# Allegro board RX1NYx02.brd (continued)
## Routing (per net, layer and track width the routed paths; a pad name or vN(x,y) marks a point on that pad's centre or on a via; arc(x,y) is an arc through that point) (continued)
GND_SIGNAL: length 26.8
  GND w0.254: 122.16,-86.62 J_S2D_TOP.1 ; J_S2D_TOP.1 123.08,-86.62 ; J_S2D_TOP.1 122.62,-87.84 ; J_S2D_TOP.1 122.62,-85.4 ; J_S2D_BOT.1 122.62,-94.29 ; J_S2D_BOT.1 123.08,-95.51 ; J_S2D_BOT.1 122.62,-96.73 ; J_S2D_BOT.1 122.16,-95.51
  VCC w0.254: 122.62,-96.73 J_S2D_BOT.1 ; J_S2D_BOT.1 123.08,-95.51 ; J_S2D_BOT.1 122.62,-94.29 ; J_S2D_BOT.1 122.16,-95.51 ; 122.16,-86.62 J_S2D_TOP.1 ; J_S2D_TOP.1 122.62,-85.4 ; J_S2D_TOP.1 122.62,-87.84 ; J_S2D_TOP.1 123.08,-86.62
  GD2 w0.254: 122.62,-96.73 J_S2D_BOT.1 ; J_S2D_BOT.1 123.08,-95.51 ; J_S2D_BOT.1 122.16,-95.51 ; J_S2D_BOT.1 122.62,-94.29 ; 122.62,-87.84 J_S2D_TOP.1 ; J_S2D_TOP.1 122.16,-86.62 ; J_S2D_TOP.1 123.08,-86.62 ; J_S2D_TOP.1 122.62,-85.4
  GD3 w0.254: J_S2D_TOP.1 123.08,-86.62 ; J_S2D_TOP.1 122.62,-85.4 ; J_S2D_TOP.1 122.62,-87.84 ; J_S2D_TOP.1 122.16,-86.62 ; 122.16,-95.51 J_S2D_BOT.1 ; J_S2D_BOT.1 123.08,-95.51 ; J_S2D_BOT.1 122.62,-94.29 ; J_S2D_BOT.1 122.62,-96.73
BD1_555_DISCHARGE: length 2.3
  TOP w0.254: R13.1 107.94,-33.08 ; R13.1 107.61,-33.4 ; R13.1 107.94,-33.73 ; R11.1 107.76,-33.86 ; R11.1 107.33,-34.29 ; R11.1 107.76,-34.73
BD1_555_OUT: length 2.4
  TOP w0.102: U4.3 R16.2 R18.2
BD1_555_OUT_JP: length 6
  TOP w0.102: P3.1 95.11,-33.53 96.38,-34.8 R16.1
BD1_555_RST_N: length 3.5
  TOP w0.102: C7.1 99.63,-36.91 99.43,-36.71 99.3,-36.71 99.17,-36.58 R15.1 99.43,-36.33 99.68,-36.07 U4.4
BD1_555_TRI: length 27.8
  TOP w0.102: R14.2 U4.2 102.22,-33.53 102.73,-34.04 102.73,-38.1 101.46,-39.37 97.14,-39.37 96.38,-40.14 96.38,-50.04 95.62,-50.8 R8.2
BD1_AUX_PWR_EN: length 7.1
  TOP w0.102: TP26.TEST 6.15,-29.47 5.18,-28.5 P_OCP1.B12
BD1_BIF0_N: length 7.4
  TOP w0.102: P_OCP1.B7 6.52,-25.5 7.63,-24.39 TP18.TEST
BD1_BIF1_N: length 10.5
  TOP w0.102: TP20.TEST 10.72,-24.59 9.65,-25.66 7.18,-25.66 6.74,-26.1 P_OCP1.B8
BD1_BIF2_N: length 6.8
  TOP w0.102: TP22.TEST 8.85,-26.9 7.51,-26.9 7.3,-26.7 P_OCP1.B9
BD1_BTN_NC: length 16.6
  TOP w0.102: U1.1 91.61,-48.28 91.81,-48.48 v1(91.81,-48.9) ; SW1.1 92.19,-40.77 91.42,-40.01 v1(91.42,-39.5) 91.17,-39.25 R7.1 R9.1
  BOTTOM w0.102: v1(91.81,-48.9) 92.44,-48.26 92.44,-40.52 v1(91.42,-39.5)
BD1_BTN_NO: length 14.3
  TOP w0.102: R17.1 94.02,-51.39 93.94,-51.31 93.46,-51.31 93.33,-51.19 R8.1 93.33,-50.8 93.33,-50.42 93.5,-50.26 SW1.3 93.5,-46.02 93.08,-45.6 91.81,-45.6 91.04,-44.83 91.04,-44.07 91.93,-43.18 91.93,-41.79 91.42,-41.28 U6.2
BD1_BUS_SEL: length 53.9
  TOP w0.102: R7.2 91.67,-38.36 92.06,-37.98 95.49,-37.98 v1(98.03,-35.44) R18.1 ; P13.1 96.07,-26.42 R158.1 96.58,-27.51 96.89,-27.82 97.39,-27.82 97.6,-28.02 C163.2 98.41,-28.96 98.57,-29.12 Q1.1 102.54,-30.42 v1(102.47,-30.48) ; U26.2 92.04,-57.52 v1(92.33,-57.23)
  BOTTOM w0.102: v1(102.47,-30.48) 100.31,-32.64 100.31,-33.15 v1(98.03,-35.44) 94.47,-38.99 94.47,-56.21 93.58,-57.1 92.46,-57.1 v1(92.33,-57.23)
BD1_CLK_NCSI: length 7.2
  BOTTOM w0.102: TP17.TEST 7.73,-18.67 6.56,-17.5 P_OCP1.OCP_A14
BD1_MAIN_PWR_EN: length 11.8
  TOP w0.102: TP27.TEST 8.32,-7.24 7.56,-8 7.56,-9.02 6.28,-10.3 P_OCP1.OCP_B2
BD1_NCSI_ARBIN: length 10.4
  BOTTOM w0.102: TP8.TEST 7.99,-12.32 7.17,-11.5 P_OCP1.OCP_A4
BD1_NCSI_ARBOUT: length 7.4
  BOTTOM w0.102: TP9.TEST 7.93,-13.59 6.44,-12.1 P_OCP1.OCP_A5
BD1_NCSI_CRS_DV: length 10.6
  TOP w0.102: P_OCP1.OCP_B14 6.64,-17.5 7.43,-18.29 10.22,-18.29 11.11,-17.4 TP16.TEST
BD1_NCSI_RXD0: length 7.4
  TOP w0.102: P_OCP1.OCP_B9 6.3,-14.5 7.93,-16.13 TP14.TEST
BD1_NCSI_RXD1: length 10.3
  TOP w0.102: TP12.TEST 7.68,-14.86 6.72,-13.9 P_OCP1.OCP_B8
BD1_NCSI_TXD0: length 11.6
  BOTTOM w0.102: P_OCP1.OCP_A9 6.36,-14.5 6.97,-15.12 6.97,-16.01 7.86,-16.89 10.72,-16.89 11.22,-17.4 TP15.TEST
BD1_NCSI_TXD1: length 8.1
  BOTTOM w0.102: P_OCP1.OCP_A8 6.52,-13.9 7.45,-14.84 7.45,-15.65 7.93,-16.13 TP13.TEST
BD1_NCSI_TXEN: length 10.8
  BOTTOM w0.102: TP11.TEST 8.24,-14.86 6.68,-13.3 P_OCP1.OCP_A7
BD1_NIC_PWR_GOOD: length 8.6
  TOP w0.102: P_OCP1.OCP_B1 6.11,-9.7 7.18,-8.64 7.18,-8 8.75,-6.43 R5.1
BD1_PERST0_N: length 10.7
  TOP w0.102: TP24.TEST 10.79,-27.13 10.03,-27.9 7.38,-27.9 6.78,-27.3 P_OCP1.B10
BD1_PERST1_N: length 10.8
  BOTTOM w0.102: TP25.TEST 11.18,-27.13 10.16,-28.15 7.5,-28.15 6.81,-27.46 3.61,-27.46 3.17,-27.9 P_OCP1.A11
BD1_PERST2_N: length 7.4
  BOTTOM w0.102: TP3.TEST 6.97,-8.51 5.78,-9.7 P_OCP1.OCP_A1
BD1_PERST3_N: length 10.1
  BOTTOM w0.102: TP4.TEST 6.33,-9.78 5.82,-10.3 P_OCP1.OCP_A2
BD1_PRSNTA_N: length 61.8
  TOP w0.102: v1(8.25,-54.44) 8.5,-54.69 R1.2 R2.2 8.5,-56.53 7.49,-57.55 7.49,-69.42 8.25,-70.19 9.91,-70.19 10.14,-70.42 R6.2 ; R3.2 v1(12.95,-28.4)
  VCC w0.102: v1(8.25,-54.44) 9.89,-52.8 9.89,-47.63 12.94,-44.58 12.94,-28.42 v1(12.95,-28.4)
  BOTTOM w0.102: v1(12.95,-28.4) 13.21,-28.15 13.21,-26.75 12.83,-26.37 11.05,-26.37 9.73,-27.69 7.8,-27.69 7.11,-27 3.43,-27 3.14,-27.3 P_OCP1.A10
BD1_PRSNTB0_N: length 10
  TOP w0.102: P_OCP1.B42 6.19,-49.91 7.75,-51.46 7.75,-54.82 8.01,-55.07
BD1_PRSNTB1_N: length 11.9
  TOP w0.102: 8.01,-55.71 v1(6.99,-55.71)
  BOTTOM w0.102: P_OCP1.A42 6.26,-49.91 7.81,-51.45 7.81,-54.25 6.99,-55.07 v1(6.99,-55.71)
BD1_PRSNTB2_N: length 9.8
  TOP w0.102: R3.1 v1(11.18,-28.4)
  BOTTOM w0.102: v1(11.18,-28.4) 10.92,-28.66 7.37,-28.66 7.21,-28.5 P_OCP1.A12
BD1_PRSNTB3_N: length 7.8
  TOP w0.102: P_OCP1.B70 6.95,-71.02 7.1,-70.87 R6.1
BD1_PWRBRK_N: length 8.1
  TOP w0.102: R164.1 v1(8.32,-69.47)
  BOTTOM w0.102: v1(8.32,-69.47) 6.78,-71.02 P_OCP1.A70
BD1_REFCLK0_DN: length 104.7
  TOP w0.099: 18.48,-21.58 18.59,-21.72 18.7,-21.74 21.2,-21.3 24.35,-21.86 26.85,-21.42 28.55,-21.72 31.05,-21.28 34.94,-21.96 38.58,-21.32 40.5,-21.66 42.98,-21.22 45.48,-21.66 48.38,-21.15 50.88,-21.59 53.72,-21.09 55.99,-21.49 61.36,-20.54 61.53,-20.31 ; 47.59,-13.36 47.59,-13.07 46.55,-12.03 46.16,-9.81 46.16,-9.25 46.06,-9.15 ; 18.25,-21.54 18.11,-21.64 16.07,-21.28 14.15,-21.62 13.7,-22.07 13.32,-24.3 13.58,-25.82 13.58,-27.4 13.26,-29.24 12.49,-30 8.66,-30.67 3.77,-29.82 3.27,-29.82 3.15,-29.7 P_OCP1.B14 ; 47.73,-13.5 48.02,-13.5 48.57,-14.05 49.48,-14.21 51.49,-13.85 53.99,-14.3 56.19,-13.91 59.01,-14.41 59.18,-14.64 ; 61.73,-20.27 61.96,-20.44 64.27,-20.03 66.21,-18.1 66.21,-16.98 64.62,-15.4 59.61,-14.51 59.38,-14.68
  TOP w0.152: 47.73,-13.5 47.59,-13.36 ; 61.53,-20.31 61.73,-20.27 ; 18.25,-21.54 18.48,-21.58 ; 46.06,-9.15 P_BD1_CLK0_N.1 ; 59.38,-14.68 59.18,-14.64
BD1_REFCLK0_DP: length 104.6
  TOP w0.099: 46.62,-9.15 46.52,-9.25 46.52,-9.78 46.88,-11.86 48,-12.98 ; 48.15,-13.12 48.74,-13.72 49.48,-13.85 51.49,-13.49 53.99,-13.93 56.19,-13.55 59.26,-14.09 ; P_OCP1.B15 3.15,-30.3 3.27,-30.17 3.74,-30.17 8.66,-31.03 12.66,-30.34 13.59,-29.41 13.94,-27.43 13.94,-25.79 13.68,-24.29 14.03,-22.24 14.33,-21.95 16.07,-21.64 18.18,-22.01 ; 59.5,-14.13 64.8,-15.06 66.56,-16.83 66.56,-18.24 64.44,-20.36 61.84,-20.82 ; 61.57,-20.87 55.99,-21.85 53.72,-21.45 50.88,-21.95 48.38,-21.51 45.48,-22.02 42.98,-21.58 40.5,-22.02 38.58,-21.68 34.94,-22.32 31.05,-21.64 28.55,-22.08 26.85,-21.78 24.35,-22.22 21.2,-21.66 18.7,-22.11 18.38,-22.05
  TOP w0.152: 59.26,-14.09 59.5,-14.13 ; 18.38,-22.05 18.18,-22.01 ; 61.84,-20.82 61.57,-20.87 ; 48,-12.98 48.15,-13.12 ; P_BD1_CLK0_P.1 46.62,-9.15
BD1_REFCLK1_DN: length 104.6
  BOTTOM w0.099: P_OCP1.A14 3.15,-29.7 3.25,-29.8 3.68,-29.8 4.74,-29.98 7.68,-29.46 10.24,-29.92 12.75,-29.48 15.25,-29.92 17.75,-29.48 20.25,-29.92 22.75,-29.48 25.25,-29.92 27.75,-29.48 30.56,-29.97 33.34,-29.48 34.72,-28.09 35.66,-22.72 36.25,-22.13 68.81,-16.39 69,-16.12 ; 91.03,-10.83 91.03,-11.15 89.44,-12.75 83.89,-13.73 83.63,-13.55 ; 69.14,-16.09 69.41,-16.28 83.29,-13.83 83.47,-13.58 ; 91.14,-10.72 91.47,-10.72 91.77,-10.42 91.88,-9.75 91.88,-9.25 91.79,-9.15
  BOTTOM w0.152: 83.63,-13.55 83.47,-13.58 ; 69.14,-16.09 69,-16.12 ; P_BD1_CLK1_N.1 91.79,-9.15 ; 91.14,-10.72 91.03,-10.83
BD1_REFCLK1_DP: length 104.6
  BOTTOM w0.099: 69.26,-16.67 83.52,-14.15 ; 91.55,-11.14 92.1,-10.59 92.24,-9.78 92.24,-9.25 92.34,-9.15 ; P_OCP1.A15 3.15,-30.3 3.29,-30.15 3.65,-30.15 4.74,-30.34 7.68,-29.83 10.24,-30.28 12.75,-29.84 15.25,-30.28 17.75,-29.84 20.25,-30.28 22.75,-29.84 25.25,-30.28 27.75,-29.84 30.56,-30.33 33.51,-29.81 35.05,-28.27 35.99,-22.89 36.42,-22.46 69.06,-16.7 ; 83.79,-14.11 89.61,-13.08 91.4,-11.29
  BOTTOM w0.152: 92.34,-9.15 P_BD1_CLK1_P.1 ; 91.4,-11.29 91.55,-11.14 ; 69.06,-16.7 69.26,-16.67 ; 83.52,-14.15 83.79,-14.11
BD1_REFCLK2_DN: length 104.7
  TOP w0.099: 56.1,-16.78 56.24,-16.68 57.24,-16.86 57.84,-17.45 57.84,-18.09 57.1,-18.83 52.3,-19.67 49.15,-19.11 47.79,-19.35 44.31,-18.74 41.74,-19.19 39.29,-18.76 36.67,-19.22 35.06,-18.94 30.2,-19.8 29.87,-19.74 27.59,-17.46 17.86,-15.77 15.28,-16.22 12.89,-15.8 11.06,-16.12 10.13,-17.05 9.44,-17.17 7.72,-17.17 6.85,-16.3 4.09,-15.82 3.27,-15.82 3.15,-15.7 P_OCP1.OCP_B11 ; 45.98,-16.67 45.82,-16.44 45.29,-16.34 42.79,-16.78 40.29,-16.34 37.79,-16.78 35.28,-16.34 32.78,-16.78 31.82,-16.62 31.58,-16.78 ; 46.18,-16.71 46.42,-16.54 47.79,-16.78 50.29,-16.34 52.79,-16.78 54.8,-16.43 55.86,-16.62 55.96,-16.76 ; 23.2,-9.15 23.3,-9.25 23.3,-9.67 23.78,-12.43 24.23,-12.88 24.23,-13.17 ; 31.38,-16.75 31.22,-16.51 27.16,-15.8 24.67,-13.31 24.38,-13.31
  TOP w0.152: P_BD1_CLK2_N.1 23.2,-9.15 ; 24.23,-13.17 24.38,-13.31 ; 55.96,-16.76 56.1,-16.78 ; 31.38,-16.75 31.58,-16.78 ; 45.98,-16.67 46.18,-16.71
BD1_REFCLK2_DP: length 104.7
  TOP w0.099: 24.83,-12.97 27.33,-15.47 31.45,-16.19 ; 46.05,-16.12 45.29,-15.98 42.79,-16.42 40.29,-15.98 37.79,-16.42 35.28,-15.98 32.78,-16.42 31.73,-16.24 ; 24.62,-12.76 24.11,-12.25 23.66,-9.64 23.66,-9.25 23.76,-9.15 ; P_OCP1.OCP_B12 3.15,-16.3 3.27,-16.18 4.05,-16.18 6.68,-16.64 7.57,-17.53 9.47,-17.53 10.31,-17.38 11.24,-16.45 12.89,-16.16 15.28,-16.58 17.86,-16.13 27.42,-17.79 29.7,-20.07 30.2,-20.16 35.06,-19.3 36.67,-19.58 39.29,-19.12 41.74,-19.55 44.31,-19.1 47.79,-19.71 49.15,-19.47 52.3,-20.03 57.27,-19.16 58.19,-18.24 58.19,-17.31 57.42,-16.53 56.22,-16.32 ; 46.32,-16.16 47.79,-16.42 50.29,-15.98 52.79,-16.42 54.8,-16.07 56.02,-16.28
  TOP w0.152: P_BD1_CLK2_P.1 23.76,-9.15 ; 46.05,-16.12 46.32,-16.16 ; 56.02,-16.28 56.22,-16.32 ; 31.45,-16.19 31.73,-16.24 ; 24.62,-12.76 24.83,-12.97
BD1_REFCLK3_DN: length 104.6
  BOTTOM w0.099: 52.66,-14.71 52.41,-14.89 52.1,-14.84 49.6,-15.28 47.99,-15 47.1,-14.84 44.6,-15.28 42.1,-14.84 39.59,-15.28 37.09,-14.84 34.59,-15.28 32.41,-14.9 30.82,-15.18 28.31,-14.74 25.23,-15.28 22.73,-14.84 20.96,-15.15 20.5,-15.62 20.5,-16.62 21.32,-17.44 23.37,-17.81 29.32,-16.76 31.31,-17.11 31.93,-17.73 31.93,-17.99 30.96,-18.96 27.91,-19.49 23.84,-18.78 21.34,-19.22 18.83,-18.78 16.33,-19.22 12.96,-18.62 12.18,-18.76 11.32,-18.76 9.91,-17.35 9.63,-17.35 8.63,-17.53 7.62,-17.35 6.56,-16.29 3.87,-15.82 3.27,-15.82 3.15,-15.7 P_OCP1.OCP_A11 ; 68.56,-11.01 68.74,-11.26 68.47,-12.87 66.26,-15.07 64.84,-15.32 63.38,-15.06 63.2,-14.81 ; 52.83,-14.74 53.01,-15 54.6,-15.28 57.1,-14.84 59.61,-15.28 62.11,-14.84 62.78,-14.96 63.03,-14.78 ; 68.93,-9.15 69.02,-9.25 69.02,-9.65 68.85,-10.66 68.59,-10.84
  BOTTOM w0.152: 68.59,-10.84 68.56,-11.01 ; 52.83,-14.74 52.66,-14.71 ; 63.2,-14.81 63.03,-14.78 ; P_BD1_CLK3_N.1 68.93,-9.15
BD1_REFCLK3_DP: length 104.7
  BOTTOM w0.099: P_OCP1.OCP_A12 3.15,-16.3 3.27,-16.18 3.83,-16.18 6.39,-16.62 7.45,-17.68 8.63,-17.89 9.66,-17.71 9.76,-17.71 11.17,-19.12 12.21,-19.12 12.96,-18.98 16.33,-19.58 18.83,-19.14 21.34,-19.58 23.84,-19.14 27.91,-19.85 31.13,-19.29 32.28,-18.14 32.28,-17.58 31.48,-16.78 29.32,-16.4 23.37,-17.44 21.49,-17.11 20.85,-16.48 20.85,-15.76 21.14,-15.48 22.73,-15.2 25.23,-15.64 28.31,-15.1 30.82,-15.54 32.41,-15.26 34.59,-15.64 37.09,-15.2 39.59,-15.64 42.1,-15.2 44.6,-15.64 47.1,-15.2 49.6,-15.64 52.1,-15.2 52.54,-15.28 ; 69.17,-10.91 69.38,-9.68 69.38,-9.25 69.48,-9.15 ; 62.91,-15.34 62.11,-15.2 59.61,-15.64 57.1,-15.2 54.6,-15.64 52.76,-15.32 ; 63.13,-15.38 64.84,-15.68 66.44,-15.4 68.8,-13.04 69.13,-11.13
  BOTTOM w0.152: 69.13,-11.13 69.17,-10.91 ; 62.91,-15.34 63.13,-15.38 ; 52.54,-15.28 52.76,-15.32 ; 69.48,-9.15 P_BD1_CLK3_P.1
BD1_SCAN_CLK: length 10.2
  TOP w0.102: P_OCP1.OCP_B6 3.13,-12.7 3.63,-12.2 11,-12.2 11.12,-12.32 TP1.TEST
BD1_SCAN_DATA_IN: length 10.8
  TOP w0.102: P_OCP1.OCP_B4 3.18,-11.5 3.51,-11.18 6.54,-11.18 7.94,-9.78 TP7.TEST
BD1_SCAN_DATA_OUT: length 7.2
  TOP w0.102: P_OCP1.OCP_B5 3.09,-12.1 3.51,-11.69 6.67,-11.69 7.3,-11.05 TP10.TEST
BD1_SCAN_LD_N: length 8.1
  TOP w0.102: P_OCP1.OCP_B3 3.15,-10.9 3.38,-10.67 6.41,-10.67 7.81,-9.27 7.81,-8.64 7.94,-8.51 TP5.TEST
BD1_SLOT_ID: length 7.1
  TOP w0.102: TP2.TEST 7.6,-13.59 7.31,-13.3 P_OCP1.OCP_B7
BD1_SMB_CLK: length 7.5
  BOTTOM w0.102: TP19.TEST 7.95,-24.39 6.7,-25.63 5.02,-25.63 4.88,-25.5 P_OCP1.A7
BD1_SMB_RST_N: length 7
  BOTTOM w0.102: P_OCP1.A9 3.1,-26.7 3.25,-26.55 7.3,-26.55 7.68,-26.93 TP23.TEST
BD1_SMB_SDA: length 10.5
  BOTTOM w0.102: TP21.TEST 10.79,-24.59 9.73,-25.66 7.81,-25.66 7.37,-26.1 P_OCP1.A8
BD1_WAKE_N: length 6.8
  BOTTOM w0.102: TP6.TEST 7.43,-11.05 7.28,-10.9 P_OCP1.OCP_A3
BD2_555_OUT: length 2.4
  TOP w0.102: U20.3 R93.2 R95.2
BD2_555_OUT_JP: length 6
  TOP w0.102: P9.1 183.02,-47.19 181.75,-45.92 R93.1
BD2_555_RST_N: length 3.5
  TOP w0.102: C81.1 178.45,-43.81 178.66,-44.02 178.78,-44.02 178.91,-44.15 R92.1 178.66,-44.4 178.4,-44.65 U20.4
BD2_555_TRI: length 27.8
  TOP w0.102: R85.2 182.47,-29.92 181.7,-30.68 181.7,-40.59 180.94,-41.35 176.62,-41.35 175.35,-42.62 175.35,-46.69 175.86,-47.19 U20.2 R91.2
BD2_AUX_PWR_EN: length 7.1
  TOP w0.102: TP81.TEST 270.65,-51.26 271.62,-52.23 P_OCP2.B12
BD2_BIF0_N: length 7.4
  TOP w0.102: TP72.TEST 270.52,-56.34 271.63,-55.23 P_OCP2.B7
BD2_BIF1_N: length 10.1
  TOP w0.102: TP73.TEST 266.04,-55.06 271.03,-55.06 271.47,-54.63 P_OCP2.B8
BD2_BIF2_N: length 6.8
  TOP w0.102: TP77.TEST 270.42,-53.8 270.65,-54.03 P_OCP2.B9
BD2_BTN_NC: length 16.6
  TOP w0.102: R86.1 R84.1 186.91,-41.47 v1(186.69,-41.26) 186.69,-40.75 185.9,-39.95 SW3.1 ; v1(186.31,-31.96) 186.8,-32.45 U17.1
  BOTTOM w0.102: v1(186.31,-31.96) 185.17,-33.1 185.17,-38.56 186.69,-40.09 v1(186.69,-41.26)
BD2_BTN_NO: length 14.3
  TOP w0.102: U22.2 186.66,-39.45 186.15,-38.94 186.15,-37.54 187.04,-36.65 187.04,-35.89 186.28,-35.13 185.01,-35.13 184.59,-34.71 SW3.3 184.59,-30.47 184.75,-30.3 184.75,-29.93 R85.1 184.75,-29.54 184.63,-29.41 184.14,-29.41 184.07,-29.34 R94.1
BD2_BUS_SEL: length 34.8
  TOP w0.102: v1(173.36,-50.25) 173.38,-50.28 Q3.1 173.54,-51.77 C165.2 178.33,-52.42 179.34,-53.44 R160.1 180.21,-53.8 180.71,-54.31 P15.1 184.73,-54.32 U27.2 ; R84.2 185.77,-42.63 183.9,-42.63 181.66,-44.86 180.52,-44.86 v1(180.09,-45.29) 180.08,-45.29 R95.1
  BOTTOM w0.102: v1(180.09,-45.29) 178.31,-45.29 v1(173.36,-50.25)
BD2_CLK_NCSI: length 7.1
  BOTTOM w0.102: P_OCP2.OCP_A14 271.68,-63.22 270.64,-62.19 TP71.TEST
BD2_MAIN_PWR_EN: length 11.8
  TOP w0.102: P_OCP2.OCP_B2 272.82,-70.42 272.56,-70.69 271.54,-70.69 270.52,-71.7 270.52,-72.72 269.76,-73.48 TP56.TEST
BD2_NCSI_ARBIN: length 10.4
  BOTTOM w0.102: P_OCP2.OCP_A4 270.92,-69.22 270.1,-68.4 TP74.TEST
BD2_NCSI_ARBOUT: length 7.4
  BOTTOM w0.102: P_OCP2.OCP_A5 271.64,-68.62 270.15,-67.13 TP62.TEST
BD2_NCSI_CRS_DV: length 10.7
  TOP w0.102: TP70.TEST 266.97,-63.32 267.96,-62.34 270.56,-62.34 271.23,-63.02 274.59,-63.02 274.79,-63.22 P_OCP2.OCP_B14
BD2_NCSI_RXD0: length 7.4
  TOP w0.102: TP68.TEST 270.15,-64.59 271.78,-66.22 P_OCP2.OCP_B9
BD2_NCSI_RXD1: length 10.3
  TOP w0.102: P_OCP2.OCP_B8 273.27,-66.82 273.06,-66.62 270.6,-66.62 269.84,-65.86 TP66.TEST
BD2_NCSI_TXD0: length 11.6
  BOTTOM w0.102: TP69.TEST 266.97,-63.32 267.48,-63.83 270.22,-63.83 271.11,-64.72 271.11,-65.61 271.73,-66.22 P_OCP2.OCP_A9
BD2_NCSI_TXD1: length 8.3
  BOTTOM w0.102: TP67.TEST 270.27,-64.59 270.65,-64.97 270.65,-65.99 271.49,-66.82 P_OCP2.OCP_A8
BD2_NCSI_TXEN: length 10.8
  BOTTOM w0.102: P_OCP2.OCP_A7 271.4,-67.42 269.84,-65.86 TP65.TEST
BD2_NIC_PWR_GOOD: length 9
  TOP w0.102: R79.1 269.87,-74.37 270.93,-73.31 270.93,-71.86 271.64,-71.15 272.71,-71.15 272.84,-71.02 P_OCP2.OCP_B1
BD2_PE_OCP_CPU_0_DN: length 104.8
  BOTTOM w0.127: 203.17,-49.37 203.29,-49.24 203.5,-49.24 207.02,-48.63 207.79,-47.87 208.47,-43.96 209.05,-43.38 209.64,-43.38 209.99,-43.72 210.11,-44.44 209.77,-46.4 210.21,-48.9 209.77,-51.4 210.21,-53.9 209.78,-56.34 210.14,-58.38 211.1,-59.34 216.06,-60.2 218.29,-59.81 220.79,-60.25 223.29,-59.81 225.79,-60.25 228.29,-59.81 230.79,-60.25 233.3,-59.81 235.8,-60.25 238.3,-59.81 239.52,-60.03 241.48,-60.03 242.49,-59.02 243.56,-52.94 245.65,-50.85 248.58,-50.34 251.08,-50.78 253.58,-50.34 255.25,-50.63 266.17,-48.71 269.94,-49.37 272.93,-48.84 274.28,-49.08 274.78,-49.08 274.93,-49.23 P_OCP2.A17
  BOTTOM w0.152: BD2_P_OCP_CPU_0_N.1 203.17,-50.73 203.17,-49.37
BD2_PE_OCP_CPU_0_DP: length 104.8
  BOTTOM w0.127: 203.17,-48.81 203.29,-48.94 203.47,-48.94 206.88,-48.35 207.51,-47.72 208.18,-43.82 208.93,-43.07 209.77,-43.07 210.27,-43.58 210.42,-44.44 210.08,-46.4 210.52,-48.9 210.08,-51.4 210.52,-53.9 210.09,-56.34 210.42,-58.23 211.25,-59.06 216.06,-59.89 218.29,-59.5 220.79,-59.94 223.29,-59.5 225.79,-59.94 228.29,-59.5 230.79,-59.94 233.3,-59.5 235.8,-59.94 238.3,-59.5 239.55,-59.72 241.35,-59.72 242.2,-58.87 243.22,-53.12 243.27,-52.79 245.51,-50.56 247.06,-50.29 248.58,-50.03 251.08,-50.47 253.58,-50.03 255.25,-50.32 266.17,-48.4 269.94,-49.06 272.93,-48.53 274.31,-48.77 274.78,-48.77 274.93,-48.63 P_OCP2.A18
  BOTTOM w0.152: 203.17,-48.81 203.17,-47.45 BD2_P_OCP_CPU_0_P.1
BD2_PERST0_N: length 10.5
  TOP w0.102: P_OCP2.B10 270.77,-53.43 269.87,-52.53 TP79.TEST
BD2_PERST1_N: length 10.4
  BOTTOM w0.102: TP80.TEST 266.11,-52.61 271.27,-52.61 271.93,-53.26 274.48,-53.26 274.91,-52.83 P_OCP2.A11
BD2_PERST2_N: length 7.4
  BOTTOM w0.102: P_OCP2.OCP_A1 271.46,-71.02 270.27,-72.21 TP55.TEST
BD2_PERST3_N: length 10.1
  BOTTOM w0.102: TP57.TEST 270.52,-70.94 271.04,-70.42 P_OCP2.OCP_A2
BD2_PRSNTA_N: length 67.2
  TOP w0.102: R82.2 v1(267.97,-5.54) ; v1(270.73,-33.1) 270.48,-32.85 R78.2 R80.2 ; R81.2 v1(265.14,-51)
  VCC w0.102: v1(267.97,-5.54) 267.27,-6.24 267.27,-29.64 v1(270.73,-33.1) 265.14,-38.68 v1(265.14,-51)
  BOTTOM w0.102: v1(265.14,-51) 265.05,-51.1 265.05,-53.47 265.24,-53.67 267.3,-53.67 267.86,-53.11 271.06,-53.11 271.67,-53.72 274.66,-53.72 274.95,-53.43 P_OCP2.A10
BD2_PRSNTB0_N: length 6.1
  TOP w0.102: R78.1 271.79,-32.33 272.06,-32.07 272.06,-31.17 272.41,-30.82 P_OCP2.B42
BD2_PRSNTB1_N: length 5.2
  TOP w0.102: R80.1 v1(271.62,-31.45)
  BOTTOM w0.102: P_OCP2.A42 272.25,-30.82 v1(271.62,-31.45)
BD2_PRSNTB2_N: length 10.2
  TOP w0.102: R81.1 v1(267.05,-51)
  BOTTOM w0.102: P_OCP2.A12 272.34,-52.23 271.75,-51.64 267.68,-51.64 v1(267.05,-51)
BD2_PRSNTB3_N: length 9.8
  TOP w0.102: R82.1 270.76,-5.54 271.14,-5.92 271.14,-8.34 272.16,-9.35 274.32,-9.35 274.67,-9.71 P_OCP2.B70
BD2_PWRBRK_N: length 8.6
  TOP w0.102: v1(270.51,-6.81) R166.1
  BOTTOM w0.102: P_OCP2.A70 271.88,-9.71 270.51,-8.33 v1(270.51,-6.81)
BD2_REFCLK0_DN: length 104.6
  TOP w0.099: 227.93,-59.87 227.76,-59.63 226.43,-59.4 223.93,-59.84 221.76,-59.46 217.23,-60.25 217.13,-60.4 ; 216.98,-60.42 216.84,-60.32 214.72,-60.7 212.55,-62.87 212.55,-64.06 214.16,-65.67 218.72,-66.48 218.94,-66.32 ; P_OCP2.B14 274.93,-51.03 274.81,-50.91 274.18,-50.91 272.32,-50.58 272.09,-50.75 ; 232.02,-71.58 231.92,-71.48 231.92,-71.26 231.62,-69.52 229.23,-67.14 226.76,-66.71 225.08,-67 222.58,-66.56 220.88,-66.86 219.32,-66.58 219.17,-66.36 ; 271.88,-50.71 271.72,-50.48 268.99,-50 266.7,-50.41 265.64,-50.22 264.97,-50.34 264.8,-50.51 264.5,-52.21 264.77,-53.72 264.47,-55.38 264.73,-58.59 264.5,-59.34 263.75,-60.1 260.25,-60.72 254.61,-59.72 252.32,-60.12 249.81,-59.68 246.71,-60.23 244.21,-59.79 242.41,-60.11 239.91,-59.67 238.93,-59.84 236.43,-59.4 233.93,-59.84 231.43,-59.4 228.93,-59.84 228.36,-59.74 228.13,-59.9
  TOP w0.152: 227.93,-59.87 228.13,-59.9 ; 271.88,-50.71 272.09,-50.75 ; 219.17,-66.36 218.94,-66.32 ; 216.98,-60.42 217.13,-60.4 ; P_BD2_CLK0_N.1 232.02,-71.58
BD2_REFCLK0_DP: length 104.6
  TOP w0.099: 218.8,-66.85 213.99,-66 212.19,-64.21 212.19,-62.72 214.55,-60.37 216.88,-59.95 ; 271.98,-50.16 268.99,-49.64 266.7,-50.05 265.64,-49.86 264.8,-50.01 264.47,-50.34 264.14,-52.21 264.4,-53.72 264.12,-55.36 264.37,-58.55 264.19,-59.16 263.58,-59.77 260.25,-60.35 254.61,-59.36 252.32,-59.76 249.81,-59.32 246.71,-59.87 244.21,-59.43 242.41,-59.75 239.91,-59.3 238.93,-59.48 236.43,-59.04 233.93,-59.48 231.43,-59.04 228.93,-59.48 228.26,-59.36 ; 219.04,-66.9 220.88,-67.22 222.58,-66.92 225.08,-67.36 226.76,-67.07 229.06,-67.47 231.29,-69.7 231.56,-71.29 231.56,-71.48 231.47,-71.58 ; 217.06,-59.92 221.76,-59.09 223.93,-59.48 226.43,-59.04 228,-59.31 ; 272.17,-50.2 274.21,-50.55 274.81,-50.55 274.93,-50.43 P_OCP2.B15
  TOP w0.152: 219.04,-66.9 218.8,-66.85 ; 271.98,-50.16 272.17,-50.2 ; P_BD2_CLK0_P.1 231.47,-71.58 ; 216.88,-59.95 217.06,-59.92 ; 228,-59.31 228.26,-59.36
BD2_REFCLK1_DN: length 104.6
  BOTTOM w0.099: 209.16,-71.58 209.06,-71.48 209.06,-70.95 208.85,-69.74 207.41,-68.31 207.41,-68.02 ; 207.27,-67.87 206.98,-67.87 205.8,-66.69 201.65,-65.96 200.48,-64.8 200.48,-63.99 202.05,-62.42 205.5,-61.81 208,-62.26 210.5,-61.81 211.66,-62.02 211.82,-62.25 ; 212.02,-62.29 212.26,-62.13 213,-62.26 215.5,-61.81 218,-62.26 220.51,-61.81 223.01,-62.26 225.51,-61.81 228.01,-62.26 230.51,-61.81 233.01,-62.26 235.51,-61.81 238.02,-62.26 243.14,-61.35 243.34,-61.32 243.58,-61.48 ; 243.78,-61.45 243.94,-61.21 252.2,-59.76 254.09,-60.09 256.59,-59.65 259.94,-60.24 263.68,-59.58 264.33,-58.94 264.55,-57.65 264.72,-57.53 ; 264.75,-57.36 264.63,-57.19 264.8,-56.26 264.27,-53.24 264.52,-51.83 264.52,-50.9 265.05,-50.37 266.33,-50.37 270.61,-51.13 273.11,-50.68 274.36,-50.91 274.81,-50.91 274.93,-51.03 P_OCP2.A14
  BOTTOM w0.152: P_BD2_CLK1_N.1 209.16,-71.58 ; 243.58,-61.48 243.78,-61.45 ; 264.72,-57.53 264.75,-57.36 ; 207.41,-68.02 207.27,-67.87 ; 211.82,-62.25 212.02,-62.29
BD2_REFCLK1_DP: length 104.6
  BOTTOM w0.099: 243.45,-60.94 238.02,-61.89 235.51,-61.45 233.01,-61.89 230.51,-61.45 228.01,-61.89 225.51,-61.45 223.01,-61.89 220.51,-61.45 218,-61.89 215.5,-61.45 213,-61.89 212.12,-61.74 ; 264.26,-57.27 264.44,-56.26 263.91,-53.24 264.16,-51.8 264.16,-50.76 264.9,-50.02 266.36,-50.02 270.61,-50.76 273.11,-50.32 274.39,-50.55 274.81,-50.55 274.93,-50.43 P_OCP2.A15 ; 211.87,-61.7 210.5,-61.45 208,-61.89 205.5,-61.45 201.88,-62.09 200.13,-63.84 200.13,-64.95 201.47,-66.29 205.62,-67.02 206.8,-68.2 ; 207.02,-68.42 208.52,-69.91 208.7,-70.98 208.7,-71.48 208.6,-71.58 ; 264.23,-57.45 264,-58.76 263.51,-59.25 259.94,-59.88 256.59,-59.29 254.09,-59.73 252.2,-59.4 243.7,-60.89
  BOTTOM w0.152: 243.45,-60.94 243.7,-60.89 ; 207.02,-68.42 206.8,-68.2 ; 264.23,-57.45 264.26,-57.27 ; 211.87,-61.7 212.12,-61.74 ; P_BD2_CLK1_P.1 208.6,-71.58
BD2_REFCLK2_DN: length 104.7
  TOP w0.099: 273.06,-64.86 273.3,-64.69 274.49,-64.9 274.81,-64.9 274.93,-65.02 P_OCP2.OCP_B11 ; 259.89,-67.43 259.98,-67.31 260.99,-67.14 261.59,-66.53 261.59,-65.92 260.68,-65 257.9,-64.51 253.87,-65.22 251.37,-64.78 250.15,-65 249.92,-64.83 ; 260.97,-63.97 260.81,-63.73 257.86,-63.21 256.84,-63.39 254.34,-62.95 251.84,-63.39 249.34,-62.95 246.84,-63.39 244.33,-62.95 241.83,-63.39 239.33,-62.95 236.83,-63.39 234.33,-62.95 231.83,-63.39 229.33,-62.95 226.93,-63.37 226.49,-63.81 226.49,-64.65 226.89,-65.05 228.37,-65.31 231.36,-64.78 233.86,-65.22 236.36,-64.78 238.86,-65.22 241.36,-64.78 243.87,-65.22 246.37,-64.78 248.87,-65.22 249.55,-65.1 249.71,-64.87 ; 259.75,-67.46 259.63,-67.37 256.67,-67.9 255.04,-69.53 254.78,-71.02 254.78,-71.48 254.88,-71.58 ; 272.86,-64.82 272.7,-64.59 270.97,-64.29 270.33,-63.65 269.54,-63.51 267.87,-63.8 266.97,-64.7 264.61,-65.12 263.16,-64.86 262.29,-64 261.41,-63.84 261.17,-64.01
  TOP w0.152: 272.86,-64.82 273.06,-64.86 ; 249.92,-64.83 249.71,-64.87 ; P_BD2_CLK2_N.1 254.88,-71.58 ; 260.97,-63.97 261.17,-64.01 ; 259.75,-67.46 259.89,-67.43
BD2_REFCLK2_DP: length 104.7
  TOP w0.099: 273.18,-64.31 274.52,-64.54 274.81,-64.54 274.93,-64.42 P_OCP2.OCP_B12 ; 261.3,-63.46 262.46,-63.67 263.33,-64.53 264.61,-64.75 266.8,-64.37 267.7,-63.47 269.54,-63.15 270.5,-63.31 271.14,-63.96 272.95,-64.27 ; 259.66,-67.01 256.5,-67.57 254.71,-69.35 254.42,-70.99 254.42,-71.48 254.32,-71.58 ; 250.07,-65.37 251.37,-65.14 253.87,-65.58 257.9,-64.87 260.51,-65.33 261.24,-66.06 261.24,-66.38 260.81,-66.8 259.85,-66.97 ; 261.05,-63.42 257.86,-62.85 256.84,-63.03 254.34,-62.59 251.84,-63.03 249.34,-62.59 246.84,-63.03 244.33,-62.59 241.83,-63.03 239.33,-62.59 236.83,-63.03 234.33,-62.59 231.83,-63.03 229.33,-62.59 226.75,-63.04 226.14,-63.66 226.14,-64.8 226.71,-65.38 228.37,-65.67 231.36,-65.14 233.86,-65.58 236.36,-65.14 238.86,-65.58 241.36,-65.14 243.87,-65.58 246.37,-65.14 248.87,-65.58 249.78,-65.42
  TOP w0.152: 259.66,-67.01 259.85,-66.97 ; 261.05,-63.42 261.3,-63.46 ; P_BD2_CLK2_P.1 254.32,-71.58 ; 272.95,-64.27 273.18,-64.31 ; 250.07,-65.37 249.78,-65.42
BD2_REFCLK3_DN: length 104.6
  BOTTOM w0.099: 238.59,-66.87 238.82,-67.04 240.14,-66.81 242.64,-67.25 245.14,-66.81 246.42,-67.03 247.06,-67.03 248.88,-66.72 249.05,-66.48 249.25,-66.45 249.48,-66.61 262.11,-64.42 262.79,-64.42 262.89,-64.32 ; 243.29,-64.83 243.52,-64.67 244.37,-64.82 246.87,-64.37 248.12,-64.6 248.96,-64.6 260.69,-62.53 260.93,-62.7 ; P_OCP2.OCP_A11 274.93,-65.02 274.81,-64.9 274.46,-64.9 273.51,-64.73 273.27,-64.9 ; 227.71,-64.73 227.55,-64.5 226.86,-64.37 225.86,-64.55 225.66,-64.54 223.19,-65.69 220.66,-65.46 220.09,-65.56 219.8,-65.85 219.8,-66.36 220.08,-66.64 223.1,-67.16 225.13,-66.81 227.63,-67.25 228.43,-67.11 228.6,-66.87 ; 227.91,-64.77 228.15,-64.6 229.36,-64.82 231.86,-64.37 234.37,-64.82 236.87,-64.37 239.37,-64.82 241.87,-64.37 242.92,-64.56 243.09,-64.8 ; 273.07,-64.86 272.91,-64.63 271.44,-64.37 270.36,-63.3 269.05,-63.3 268.6,-63.38 268.02,-63.3 267.21,-62.49 265.92,-62.26 264.4,-62.53 262.55,-62.2 261.29,-62.42 261.13,-62.66 ; 228.8,-66.84 229.04,-67 230.13,-66.81 232.63,-67.25 235.13,-66.81 237.63,-67.25 238.22,-67.15 238.39,-66.91
  BOTTOM w0.152: 243.09,-64.8 243.29,-64.83 ; 273.07,-64.86 273.27,-64.9 ; 238.59,-66.87 238.39,-66.91 ; 260.93,-62.7 261.13,-62.66 ; 227.71,-64.73 227.91,-64.77 ; 228.8,-66.84 228.6,-66.87 ; TP82.TEST 262.89,-64.32
BD2_REFCLK3_DP: length 104.6
  BOTTOM w0.099: 228.68,-67.42 227.63,-67.61 225.13,-67.17 223.1,-67.52 219.91,-66.97 219.45,-66.51 219.45,-65.7 219.92,-65.23 220.64,-65.1 223.12,-65.32 225.6,-64.17 225.84,-64.19 226.86,-64.01 227.82,-64.18 ; 261.05,-62.11 262.55,-61.84 264.4,-62.17 265.92,-61.9 267.38,-62.16 268.18,-62.96 268.59,-63.02 269.02,-62.94 270.51,-62.94 271.61,-64.04 273.14,-64.31 ; 238.42,-67.47 237.63,-67.61 235.13,-67.17 232.63,-67.61 230.13,-67.17 228.93,-67.38 ; 273.34,-64.35 274.49,-64.54 274.81,-64.54 274.93,-64.42 P_OCP2.OCP_A12 ; 262.89,-64.88 262.79,-64.78 262.14,-64.78 247.09,-67.39 246.39,-67.39 245.14,-67.17 242.64,-67.61 240.14,-67.17 238.7,-67.42 ; 243.16,-64.24 241.87,-64.01 239.37,-64.45 236.87,-64.01 234.37,-64.45 231.86,-64.01 229.36,-64.45 228.03,-64.22 ; 243.36,-64.28 244.37,-64.45 246.87,-64.01 248.15,-64.24 248.93,-64.24 260.83,-62.15
  BOTTOM w0.152: 243.16,-64.24 243.36,-64.28 ; 227.82,-64.18 228.03,-64.22 ; TP83.TEST 262.89,-64.88 ; 273.14,-64.31 273.34,-64.35 ; 238.7,-67.42 238.42,-67.47 ; 260.83,-62.15 261.05,-62.11 ; 228.93,-67.38 228.68,-67.42
BD2_SCAN_CLK: length 10.1
  TOP w0.102: P_OCP2.OCP_B6 273.06,-68.02 272.68,-68.4 TP63.TEST
BD2_SCAN_DATA_IN: length 10.8
  TOP w0.102: TP60.TEST 270.14,-70.94 271.29,-69.8 272.43,-69.8 273.01,-69.22 P_OCP2.OCP_B4
BD2_SCAN_DATA_OUT: length 7.2
  TOP w0.102: P_OCP2.OCP_B5 273.09,-68.62 272.43,-69.29 271.16,-69.29 270.77,-69.67 TP61.TEST
BD2_SCAN_LD_N: length 7.7
  TOP w0.102: TP58.TEST 271.12,-70.3 272.43,-70.3 272.91,-69.82 P_OCP2.OCP_B3
BD2_SLOT_ID: length 7.1
  TOP w0.102: P_OCP2.OCP_B7 273.23,-67.42 272.94,-67.13 TP64.TEST
BD2_SMB_CLK: length 7.4
  BOTTOM w0.102: P_OCP2.A7 273.15,-55.23 273.11,-55.19 271.29,-55.19 270.14,-56.34 TP75.TEST
BD2_SMB_RST_N: length 7
  BOTTOM w0.102: TP78.TEST 270.91,-53.8 271.29,-54.17 274.83,-54.17 274.98,-54.03 P_OCP2.A9
BD2_SMB_SDA: length 10.1
  BOTTOM w0.102: TP76.TEST 270.73,-55.07 271.12,-54.68 274.84,-54.68 274.9,-54.63 P_OCP2.A8
BD2_WAKE_N: length 6.8
  BOTTOM w0.102: P_OCP2.OCP_A3 270.67,-69.82 270.52,-69.67 TP59.TEST
CLK1_HOST_TO_TRIGGER_DN: length 11.2
  TOP w0.127: U24.2 90.88,-65.67 90.78,-65.57 90.28,-65.57 89.78,-66.07 89.24,-66.07 C149.2 88.38,-66.07 86.52,-66.07 86.34,-66.25
  TOP w0.152: P_BD1_TRIG_IN_N.1 86.34,-66.25
CLK1_HOST_TO_TRIGGER_DP: length 11.2
  TOP w0.127: 86.34,-65.59 86.52,-65.76 88.38,-65.76 C148.2 89.24,-65.76 89.65,-65.76 90.15,-65.26 90.78,-65.26 90.88,-65.17 U24.1
  TOP w0.152: P_BD1_TRIG_IN_P.1 86.34,-65.59
CLK1_TRIG_SIGNAL_C_DN: length 1.4
  TOP w0.127: C12.1 96.32,-65.79 96.96,-65.79 97.09,-65.66 R21.1
CLK1_TRIG_SIGNAL_C_DP: length 1.4
  TOP w0.127: C11.1 96.3,-66.09 96.96,-66.09 97.09,-66.22 R19.1
CLK1_TRIG_SIGNAL_DN: length 1.3
  TOP w0.127: U24.11 95.02,-65.67 95.12,-65.76 95.44,-65.76 C12.2
CLK1_TRIG_SIGNAL_DP: length 1.3
  TOP w0.127: C11.2 95.42,-66.07 95.12,-66.07 95.02,-66.17 U24.10
CLK1_TRIG_SIGNAL_R_DN: length 6.7
  TOP w0.127: R21.2 98.36,-65.76 98.92,-65.76 99.04,-65.64
  TOP w0.152: P_BD1_CMTS_N.1 99.04,-65.64
CLK1_TRIG_SIGNAL_R_DP: length 6.8
  TOP w0.127: R19.2 98.38,-66.07 98.92,-66.07 99.04,-66.2
  TOP w0.152: P_BD1_CMTS_P.1 99.04,-66.2
CLK2_HOST_TO_TRIGGER_DN: length 11.2
  TOP w0.127: 179.04,-66.19 179.21,-66.01 181.07,-66.01 C158.2 181.93,-66.01 182.47,-66.01 182.97,-65.51 183.47,-65.51 183.57,-65.61 U25.2
  TOP w0.152: P_BD2_TRIG_IN_N.1 179.04,-66.19
CLK2_HOST_TO_TRIGGER_DP: length 11.2
  TOP w0.127: 179.04,-65.53 179.21,-65.71 181.07,-65.71 C156.2 181.93,-65.71 182.35,-65.71 182.85,-65.21 183.47,-65.21 183.57,-65.11 U25.1
  TOP w0.152: P_BD2_TRIG_IN_P.1 179.04,-65.53
CLK2_TRIG_SIGNAL_C_DN: length 1.4
  TOP w0.127: R99.1 189.78,-65.61 189.65,-65.74 189.02,-65.74 C90.1
CLK2_TRIG_SIGNAL_C_DP: length 1.4
  TOP w0.127: C86.1 188.99,-66.04 189.65,-66.04 189.78,-66.17 R96.1
CLK2_TRIG_SIGNAL_DN: length 1.3
  TOP w0.127: U25.11 187.71,-65.61 187.81,-65.71 188.13,-65.71 C90.2
CLK2_TRIG_SIGNAL_DP: length 1.3
  TOP w0.127: C86.2 188.11,-66.01 187.81,-66.01 187.71,-66.11 U25.10
CLK2_TRIG_SIGNAL_R_DN: length 6.7
  TOP w0.127: 191.74,-65.58 191.61,-65.71 191.05,-65.71 R99.2
  TOP w0.152: P_BD2_CMTS_N.1 191.74,-65.58
CLK2_TRIG_SIGNAL_R_DP: length 6.8
  TOP w0.127: 191.74,-66.14 191.61,-66.01 191.08,-66.01 R96.2
  TOP w0.152: P_BD2_CMTS_P.1 191.74,-66.14
PE_CAL_BOT_OCP_CPU_0_DN: length 104.8
  BOTTOM w0.127: 90.4,79.8 90.53,79.93 90.53,80.23 90.94,82.6 92.09,83.76 95.71,84.39 97.12,84.14 99.62,84.58 102.12,84.14 103.95,84.46 104.9,85.42 104.9,86.15 104.48,86.58 102.93,86.85 101.9,86.66 99.4,87.11 96.9,86.66 94.4,87.11 91.9,86.66 89.4,87.11 86.9,86.66 84.39,87.11 81.89,86.66 79.39,87.11 76.89,86.66 74.39,87.11 72.29,86.74 70.26,87.09 69.29,88.06 69.29,88.72 70.39,89.81 71.99,90.09 73.81,89.77 76.31,90.21 78.81,89.77 81.31,90.21 83.81,89.77 86.31,90.21 88.81,89.77 91.32,90.21 93.82,89.77 96.32,90.21 98.82,89.77 103.41,90.58 107.58,94.75 107.72,95.59 107.72,95.97 107.58,96.12 P_OCPSTRDL.A17
  BOTTOM w0.152: P_CAL_OCP_CPU_B_0_N.1 90.4,79.8
PE_CAL_BOT_OCP_CPU_0_DP: length 104.8
  BOTTOM w0.127: P_OCPSTRDL.A18 108.18,96.12 108.03,95.97 108.03,95.57 107.86,94.6 103.56,90.3 98.82,89.46 96.32,89.9 93.82,89.46 91.32,89.9 88.81,89.46 86.31,89.9 83.81,89.46 81.31,89.9 78.81,89.46 76.31,89.9 73.81,89.46 71.99,89.78 70.54,89.53 69.6,88.59 69.6,88.19 70.41,87.38 72.29,87.04 74.39,87.42 76.89,86.97 79.39,87.42 81.89,86.97 84.39,87.42 86.9,86.97 89.4,87.42 91.9,86.97 94.4,87.42 96.9,86.97 99.4,87.42 101.9,86.97 102.93,87.16 104.63,86.86 105.21,86.28 105.21,85.29 104.1,84.18 102.12,83.83 99.62,84.27 97.12,83.83 95.71,84.08 92.24,83.48 91.22,82.46 90.83,80.2 90.83,79.93 90.96,79.8
  BOTTOM w0.152: P_CAL_OCP_CPU_B_0_P.1 90.96,79.8
PE_CAL_CPU_OCP_0_DN: length 58.9
  TOP w0.127: 128.5,79.8 128.63,79.93 128.63,80.72 128.81,81.79 131.76,84.74 132.46,88.76 132.41,89.08 130.59,90.9 128.51,91.27 123.9,90.45 121.4,90.9 118.9,90.45 116.55,90.87 115.44,90.67 115.19,90.67 109.68,85.16 108.8,85.16 107.55,84.94 105.66,85.28 105.09,85.84 105.09,86.68 106.42,88.01 106.8,90.24 107.19,91.31 107.19,93.6 107.57,94.67 107.72,95.54 107.72,95.97 107.58,96.12 P_OCPSTRDL.B17
  TOP w0.152: 128.5,79.8 P_CAL_CPU_OCP_0_N1.1
PE_CAL_CPU_OCP_0_DP: length 58.9
  TOP w0.127: 129.06,79.8 128.93,79.93 128.93,80.7 129.1,81.64 132.04,84.59 132.77,88.76 132.69,89.22 130.73,91.18 128.51,91.58 123.9,90.76 121.4,91.2 118.9,90.76 116.55,91.18 115.42,90.98 115.06,90.98 109.55,85.47 108.77,85.47 107.55,85.25 105.8,85.56 105.39,85.97 105.39,86.55 106.7,87.86 107.1,90.16 107.5,91.26 107.49,93.55 107.87,94.6 108.03,95.51 108.03,95.97 108.18,96.12 P_OCPSTRDL.B18
  TOP w0.152: 129.06,79.8 P_CAL_CPU_OCP_0_P1.1
PE_CPU_OCP_0_DN: length 59
  TOP w0.127: 8.6,-32.66 8.51,-32.82 8.23,-32.89 6.65,-32.47 6.56,-32.31 ; 23.2,-25.91 23.33,-26.04 23.33,-26.88 23.07,-27.13 22.77,-27.13 22.07,-26.95 21.36,-27.13 20.95,-27.13 20.65,-27.44 20.65,-28.48 20.95,-28.78 21.77,-28.78 22.05,-28.71 22.32,-28.78 23.53,-28.78 24.71,-28.48 25.88,-28.78 26.29,-28.78 26.97,-29.47 27.32,-29.47 28.24,-29.71 29.17,-29.47 30.09,-29.47 31.48,-29.83 32.87,-29.47 33.33,-29.47 33.45,-29.59 33.45,-30.46 33.3,-30.65 31.59,-31.09 29.81,-30.64 29.13,-30.64 27.29,-31.13 26.37,-30.88 26.3,-30.75 ; 18.71,-29.91 18.58,-29.99 16.98,-29.56 15.71,-29.9 14.66,-29.9 12.32,-32.24 11.66,-32.24 11.17,-32.11 10.71,-32.23 10.56,-32.15 ; 10.35,-32.21 10.26,-32.35 8.95,-32.7 8.79,-32.61 ; 18.89,-29.95 18.97,-30.09 19.43,-30.22 20.62,-29.9 20.97,-29.9 22.07,-30.09 23.41,-29.86 23.65,-29.9 24.03,-29.9 24.76,-30.64 25.45,-30.64 25.93,-30.77 26.06,-30.69 ; P_OCP1.B17 3.15,-31.5 3.31,-31.65 4.5,-31.65 5.08,-32.24 5.78,-32.24 6.21,-32.35 6.36,-32.26
  TOP w0.152: 18.89,-29.95 18.71,-29.91 ; P_CPU_OCP_0_N.1 23.2,-25.91 ; 26.3,-30.75 26.06,-30.69 ; 10.56,-32.15 10.35,-32.21 ; 8.79,-32.61 8.6,-32.66 ; 6.56,-32.31 6.36,-32.26
PE_CPU_OCP_0_DP: length 59
  TOP w0.127: 18.74,-30.35 19.43,-30.53 20.66,-30.2 20.94,-30.2 22.07,-30.4 23.41,-30.17 23.62,-30.2 23.9,-30.2 24.64,-30.94 25.41,-30.94 25.98,-31.09 ; 8.91,-33.03 10.45,-32.62 ; 8.66,-33.09 8.23,-33.21 6.42,-32.72 ; P_OCP1.B18 3.15,-32.1 3.29,-31.96 4.37,-31.96 4.95,-32.54 5.74,-32.54 6.25,-32.68 ; 26.17,-31.15 27.29,-31.44 29.17,-30.94 29.77,-30.94 31.59,-31.41 33.48,-30.92 33.76,-30.56 33.76,-29.47 33.45,-29.16 32.83,-29.16 31.48,-29.51 30.12,-29.16 29.13,-29.16 28.24,-29.39 27.36,-29.16 27.1,-29.16 26.42,-28.48 25.92,-28.48 24.71,-28.16 23.49,-28.48 22.36,-28.48 22.05,-28.39 21.73,-28.48 21.08,-28.48 20.95,-28.35 20.95,-27.56 21.08,-27.44 21.4,-27.44 22.07,-27.26 22.73,-27.44 23.2,-27.44 23.63,-27 23.63,-26.04 23.76,-25.91 ; 18.6,-30.31 16.98,-29.88 15.75,-30.2 14.78,-30.2 12.45,-32.54 11.62,-32.54 11.17,-32.42 10.67,-32.56
  TOP w0.152: 6.25,-32.68 6.42,-32.72 ; 23.76,-25.91 P_CPU_OCP_0_P.1 ; 25.98,-31.09 26.17,-31.15 ; 10.45,-32.62 10.67,-32.56 ; 18.6,-30.31 18.74,-30.35 ; 8.66,-33.09 8.91,-33.03
PE_CPU_OCP_1_DN: length 58.9
  TOP w0.127: 28.16,-32.93 28,-33.02 27.07,-32.77 25.23,-33.26 24.75,-33.26 22.99,-31.5 21.73,-31.5 20.84,-31.35 20.52,-31.35 19.43,-31.64 16.98,-30.98 15.89,-31.27 15.19,-31.27 12.65,-33.81 11.46,-33.81 11.18,-33.74 10.17,-34.01 10.01,-33.92 ; 46.04,-25.91 46.18,-26.03 46.18,-26.58 45.76,-28.22 46.18,-29.87 46.18,-30.58 43.5,-33.26 42.75,-33.26 41.35,-32.9 38.11,-33.76 36.73,-33.39 36.64,-33.23 ; 32.01,-33.29 32.16,-33.38 34.43,-32.77 36.29,-33.27 36.44,-33.18 ; 28.35,-32.98 28.44,-33.14 30.75,-33.76 31.72,-33.5 31.81,-33.34 ; P_OCP1.B20 3.15,-33.3 3.3,-33.44 4.26,-33.44 4.62,-33.81 5.57,-33.81 6.55,-34.07 6.7,-33.98 ; 6.9,-34.03 6.99,-34.19 8.23,-34.52 9.72,-34.13 9.81,-33.97
  TOP w0.152: 36.64,-33.23 36.44,-33.18 ; P_CPU_OCP_1_N.1 46.04,-25.91 ; 32.01,-33.29 31.81,-33.34 ; 6.9,-34.03 6.7,-33.98 ; 28.35,-32.98 28.16,-32.93 ; 10.01,-33.92 9.81,-33.97
PE_CPU_OCP_1_DP: length 58.9
  TOP w0.127: 46.62,-25.91 46.6,-25.91 46.49,-26.03 46.49,-26.61 46.07,-28.22 46.49,-29.84 46.49,-30.71 43.62,-33.57 42.71,-33.57 41.35,-33.22 38.11,-34.07 36.51,-33.64 ; 9.91,-34.39 8.23,-34.84 6.77,-34.45 ; 31.96,-33.75 30.75,-34.07 28.22,-33.39 ; 10.08,-34.34 11.18,-34.05 11.42,-34.12 12.78,-34.12 15.32,-31.58 15.93,-31.58 16.98,-31.3 19.43,-31.95 20.56,-31.65 20.82,-31.65 21.71,-31.81 22.86,-31.81 24.63,-33.57 25.27,-33.57 27.07,-33.09 28.07,-33.36 ; 36.32,-33.59 34.43,-33.09 32.11,-33.71 ; P_OCP1.B21 3.15,-33.9 3.3,-33.75 4.13,-33.75 4.5,-34.12 5.53,-34.12 6.57,-34.39
  TOP w0.152: 32.11,-33.71 31.96,-33.75 ; 6.77,-34.45 6.57,-34.39 ; P_CPU_OCP_1_P.1 46.62,-25.91 ; 28.22,-33.39 28.07,-33.36 ; 10.08,-34.34 9.91,-34.39 ; 36.51,-33.64 36.32,-33.59
PE_CPU_OCP_2_DN: length 58.9
  TOP w0.127: 29.19,-42.78 29.07,-42.9 28.53,-42.9 26.92,-42.62 25.98,-41.68 24.69,-41.68 24.08,-42.29 24.08,-42.72 24.53,-45.25 24.17,-47.26 24.47,-48.95 24.31,-49.86 23.95,-50.22 22.77,-50.22 22.24,-49.69 21.85,-47.47 22.27,-45.05 22.04,-43.72 22.45,-41.4 22.02,-38.97 22.53,-36.06 22.13,-33.79 21.69,-33.35 20.99,-33.35 20.75,-33.29 19.31,-33.67 16.86,-33.01 15.59,-33.35 15.11,-33.35 13.22,-35.24 11.28,-35.24 11.18,-35.22 8.23,-36.01 5.38,-35.24 3.3,-35.24 3.15,-35.1 P_OCP1.B23
  TOP w0.152: 29.19,-42.78 P_CPU_OCP_2_N.1
PE_CPU_OCP_2_DP: length 58.9
  TOP w0.127: P_OCP1.B24 3.15,-35.7 3.3,-35.55 5.34,-35.55 8.23,-36.32 11.19,-35.54 11.24,-35.55 13.35,-35.55 15.24,-33.66 15.63,-33.66 16.86,-33.33 19.31,-33.99 20.75,-33.6 20.95,-33.66 21.56,-33.66 21.85,-33.94 22.22,-36.06 21.71,-38.97 22.14,-41.4 21.73,-43.72 21.96,-45.05 21.54,-47.47 21.95,-49.84 22.64,-50.52 24.07,-50.52 24.59,-50.01 24.78,-48.95 24.48,-47.26 24.83,-45.25 24.38,-42.7 24.38,-42.42 24.82,-41.99 25.85,-41.99 26.77,-42.91 28.5,-43.21 29.07,-43.21 29.19,-43.34
  TOP w0.152: 29.19,-43.34 P_CPU_OCP_2_P.1
PE_CPU_OCP_3_DN: length 58.9
  TOP w0.127: P_OCP1.B26 3.15,-36.9 3.3,-37.04 4.62,-37.04 8.25,-37.42 11.3,-36.66 11.57,-36.66 12.45,-36.88 13.32,-36.66 13.64,-36.66 14.26,-37.28 14.26,-38.36 13.5,-39.12 12.79,-39.12 11.1,-38.68 9.41,-39.12 8.68,-39.12 8.55,-39.25 8.55,-40.14 8.68,-40.26 9.21,-40.26 11.09,-39.76 14.13,-40.56 15.29,-40.26 16.41,-40.26 16.71,-40.57 16.71,-41.32 16.01,-42.02 15.41,-42.02 13.53,-42.52 11.1,-41.88 10.96,-41.91 10.93,-41.95 10.82,-41.95 10.55,-42.02 10.38,-42.02 9.68,-42.73 9.68,-43.16 9.94,-43.42 11.08,-44.09 11.75,-45.23 11.81,-45.29 12.32,-45.29 12.45,-45.16 12.45,-44.03 12.91,-43.57 13.86,-43.57 14.35,-44.06 14.35,-44.4 14.51,-45.02 14.35,-45.63 14.35,-45.72 14.63,-46 15.77,-46 16.13,-45.65 16.13,-45.48 15.9,-44.61 16.13,-43.73 16.13,-43.39 16.61,-42.9 17.64,-42.9 17.76,-42.78
  TOP w0.152: 17.76,-42.78 P_CPU_OCP_3_N.1
PE_CPU_OCP_3_DP: length 58.9
  TOP w0.127: 17.76,-43.34 17.64,-43.21 16.74,-43.21 16.43,-43.51 16.43,-43.77 16.22,-44.61 16.43,-45.45 16.43,-45.77 15.9,-46.31 14.5,-46.31 14.05,-45.85 14.05,-45.6 14.2,-45.02 14.05,-44.44 14.05,-44.19 13.74,-43.87 13.04,-43.87 12.75,-44.16 12.75,-45.29 12.45,-45.6 11.68,-45.6 11.51,-45.42 10.85,-44.31 9.75,-43.66 9.37,-43.28 9.37,-42.6 10.26,-41.72 10.51,-41.72 11.1,-41.56 13.53,-42.21 15.37,-41.72 15.89,-41.72 16.41,-41.2 16.41,-40.7 16.28,-40.57 15.33,-40.57 14.13,-40.88 11.09,-40.08 9.25,-40.57 8.55,-40.57 8.25,-40.26 8.25,-39.13 8.56,-38.82 9.37,-38.82 11.1,-38.37 12.83,-38.82 13.37,-38.82 13.95,-38.24 13.95,-37.4 13.51,-36.96 13.36,-36.96 12.45,-37.2 11.53,-36.96 11.34,-36.96 8.28,-37.73 4.59,-37.35 4.13,-37.35 3.3,-37.35 3.15,-37.5 P_OCP1.B27
  TOP w0.152: 17.76,-43.34 P_CPU_OCP_3_P.1
PE_CPU_OCP_4_DN: length 58.9
  TOP w0.127: P_OCP1.B30 3.15,-42.71 3.3,-42.85 4.19,-42.85 5.62,-42.48 7.05,-42.85 7.39,-42.85 14.49,-49.95 14.49,-51.11 15.66,-52.28 16.42,-52.28 18.26,-52.77 21.94,-51.78 25.63,-52.77 29.31,-51.78 32.67,-52.67 34,-52.33 34.72,-52.33 35.2,-51.84 35.2,-51.65 34.7,-49.77 35.69,-46.09 35.15,-44.06 35.2,-43.84 35.2,-43.36 36.08,-42.48 37.29,-42.48 37.71,-42.9 37.96,-42.9 38.96,-43.16 39.96,-42.9 40.5,-42.9 40.62,-42.78
  TOP w0.152: 40.62,-42.78 P_CPU_OCP_4_N.1
PE_CPU_OCP_4_DP: length 58.9
  TOP w0.127: P_OCP1.B31 3.15,-43.31 3.3,-43.16 4.23,-43.16 5.62,-42.8 7.01,-43.16 7.27,-43.16 14.19,-50.08 14.19,-51.23 15.53,-52.58 16.38,-52.58 18.26,-53.09 21.94,-52.1 25.63,-53.09 29.31,-52.1 32.67,-52.99 34.04,-52.63 34.85,-52.63 35.51,-51.97 35.51,-51.61 35.02,-49.77 36,-46.09 35.46,-44.06 35.51,-43.88 35.51,-43.49 36.21,-42.79 37.16,-42.79 37.58,-43.21 37.92,-43.21 38.96,-43.48 40,-43.21 40.5,-43.21 40.62,-43.34
  TOP w0.152: 40.62,-43.34 P_CPU_OCP_4_P.1
PE_CPU_OCP_5_DN: length 58.9
  TOP w0.127: 40.62,-65.64 40.5,-65.76 40.11,-65.76 38.35,-65.45 36.17,-65.84 34.46,-65.54 33.76,-64.83 33.76,-64.62 34.15,-62.41 33.62,-59.44 33.99,-57.37 31.15,-54.54 28.72,-53.89 25.04,-54.88 21.36,-53.89 17.68,-54.88 15.84,-54.38 15.09,-54.38 12.88,-52.17 12.88,-50.75 6.78,-44.65 6.44,-44.65 5.09,-44.31 3.74,-44.65 3.3,-44.65 3.15,-44.51 P_OCP1.B33
  TOP w0.152: 40.62,-65.64 P_CPU_OCP_5_N.1
PE_CPU_OCP_5_DP: length 58.9
  TOP w0.127: 40.62,-66.2 40.5,-66.07 40.08,-66.07 38.35,-65.76 36.17,-66.15 34.32,-65.82 33.45,-64.95 33.45,-64.6 33.84,-62.41 33.31,-59.44 33.66,-57.48 31,-54.81 28.72,-54.21 25.04,-55.19 21.36,-54.21 17.68,-55.19 15.8,-54.69 14.96,-54.69 12.57,-52.3 12.57,-50.88 6.65,-44.96 6.4,-44.96 5.09,-44.62 3.78,-44.96 3.3,-44.96 3.15,-45.11 P_OCP1.B34
  TOP w0.152: 40.62,-66.2 P_CPU_OCP_5_P.1
PE_CPU_OCP_6_DN: length 59
  TOP w0.127: P_OCP1.B36 3.15,-46.31 3.3,-46.45 4,-46.45 5.1,-46.17 6.21,-46.45 6.55,-46.45 11.47,-51.38 11.47,-53.71 14,-56.24 14.71,-56.24 16.51,-56.72 19.62,-55.9 20.69,-56.18 22.67,-58.15 22.81,-58.97 22.31,-61.79 22.76,-64.29 22.31,-66.79 22.76,-69.29 22.4,-71.32 22.55,-72.15 22.89,-72.49 24.21,-72.49 24.69,-72.01 24.69,-71.16 24.39,-69.46 24.61,-68.19 24.61,-67.62 26.09,-66.15 28.29,-65.76 29.07,-65.76 29.19,-65.64
  TOP w0.152: 29.19,-65.64 P_CPU_OCP_6_N.1
PE_CPU_OCP_6_DP: length 58.9
  TOP w0.127: P_OCP1.B37 3.15,-46.91 3.3,-46.76 4.04,-46.76 5.1,-46.48 6.17,-46.76 6.42,-46.76 11.16,-51.5 11.16,-53.84 13.87,-56.54 14.67,-56.54 16.51,-57.04 19.62,-56.22 20.54,-56.45 22.38,-58.3 22.5,-58.97 22,-61.79 22.45,-64.29 22,-66.79 22.45,-69.29 22.09,-71.32 22.26,-72.3 22.76,-72.8 24.33,-72.8 24.99,-72.14 24.99,-71.13 24.7,-69.46 25.02,-67.64 26.23,-66.43 28.31,-66.07 29.07,-66.07 29.19,-66.2
  TOP w0.152: 29.19,-66.2 P_CPU_OCP_6_P.1
PE_CPU_OCP_7_DN: length 58.9
  TOP w0.127: P_OCP1.B39 3.15,-48.11 3.3,-48.25 3.64,-48.25 4.87,-47.94 6.1,-48.25 6.44,-48.25 9.96,-51.77 9.96,-53.37 10.45,-55.21 9.46,-58.89 10.45,-62.57 9.9,-64.63 9.96,-64.85 9.96,-65.11 11.66,-66.81 12.09,-69.23 11.65,-71.73 11.95,-73.46 11.81,-74.26 11.81,-74.45 12.3,-74.94 12.85,-74.94 13.41,-74.38 13.41,-74 13.2,-72.81 13.54,-70.87 12.64,-65.73 11.89,-64.98 11.89,-63.76 12.27,-63.38 13.31,-63.38 15.7,-65.76 17.64,-65.76 17.76,-65.64
  TOP w0.152: 17.76,-65.64 P_CPU_OCP_7_N.1
PE_CPU_OCP_7_DP: length 58.9
  TOP w0.127: P_OCP1.B40 3.15,-48.71 3.3,-48.56 3.68,-48.56 4.87,-48.25 6.06,-48.56 6.32,-48.56 9.65,-51.9 9.65,-53.41 10.13,-55.21 9.15,-58.89 10.13,-62.57 9.58,-64.63 9.65,-64.89 9.65,-65.23 11.38,-66.96 11.78,-69.23 11.34,-71.73 11.64,-73.46 11.51,-74.23 11.51,-74.58 12.17,-75.25 12.97,-75.25 13.72,-74.5 13.72,-73.97 13.51,-72.81 13.85,-70.87 13.85,-70.81 12.92,-65.58 12.19,-64.85 12.19,-63.88 12.39,-63.68 13.18,-63.68 15.57,-66.07 17.64,-66.07 17.76,-66.2
  TOP w0.152: 17.76,-66.2 P_CPU_OCP_7_P.1
PE_CPU_OCP_8_DN: length 58.9
  TOP w0.127: P_OCP2.B44 274.93,-25.31 274.78,-25.16 274.41,-25.16 273.69,-25.03 271.86,-25.35 271.63,-25.48 270.07,-27.04 269.14,-30.8 269.14,-34.35 270.61,-35.82 270.61,-37.14 269.65,-38.11 269.28,-38.11 268.74,-38.01 268.2,-38.11 267.96,-38.11 267.51,-38.56 267.51,-39.06 267.72,-39.27 267.83,-39.27 268.27,-39.35 268.71,-39.27 269.11,-39.27 269.84,-40 269.84,-40.81 269.12,-41.53 267.55,-41.8 265.73,-41.48 265.08,-41.48 264.49,-42.07 264.49,-42.63 265.13,-43.26 265.52,-43.26 267.5,-42.91 269.46,-43.26 271.02,-44.82 271.25,-46.18 271.06,-47.31 270.15,-48.22 269.37,-48.22 268.15,-48 262.54,-48.99 261.52,-50.01 260.44,-50.01 260.32,-50.14
  TOP w0.152: 260.32,-50.14 P_CPU_OCP_8_N.1
PE_CPU_OCP_8_DP: length 58.9
  TOP w0.127: P_OCP2.B45 274.93,-24.71 274.78,-24.85 274.44,-24.85 273.69,-24.72 271.75,-25.06 271.45,-25.23 269.79,-26.89 268.83,-30.77 268.83,-34.47 270.31,-35.95 270.31,-37.01 269.52,-37.8 269.31,-37.8 268.74,-37.7 268.17,-37.8 267.83,-37.8 267.2,-38.43 267.2,-39.19 267.59,-39.58 267.8,-39.58 268.27,-39.66 268.73,-39.58 268.99,-39.58 269.54,-40.13 269.54,-40.68 268.97,-41.25 267.55,-41.49 265.76,-41.18 264.95,-41.18 264.19,-41.94 264.19,-42.75 265,-43.57 265.55,-43.57 267.5,-43.22 269.31,-43.54 270.73,-44.96 270.94,-46.18 270.77,-47.16 270.03,-47.91 269.4,-47.91 268.15,-47.69 262.4,-48.71 261.39,-49.71 260.44,-49.71 260.32,-49.58
  TOP w0.152: 260.32,-49.58 P_CPU_OCP_8_P.1
PE_CPU_OCP_9_DN: length 59
  TOP w0.127: P_OCP2.B47 274.93,-23.51 274.78,-23.36 274.3,-23.36 273.48,-23.19 271.38,-23.92 270.68,-24.48 268.8,-26.31 265.5,-37.85 264.12,-38.98 263.72,-39.05 262.82,-39.04 260.9,-39.71 258.62,-39.68 257.54,-40.05 257.24,-40.1 256.35,-41 256.13,-42.25 256.43,-43.96 255.91,-46.9 256.39,-49.63 256.1,-51.3 256.18,-51.81 256.18,-52.94 255.07,-54.05 254.14,-54.05 253.58,-53.49 253.05,-50.43 252.32,-49.71 251.43,-49.48 249.37,-50.01 249.01,-50.01 248.89,-50.14
  TOP w0.152: 248.89,-50.14 P_CPU_OCP_9_N.1
PE_CPU_OCP_9_DP: length 58.9
  TOP w0.127: P_OCP2.B48 274.93,-22.91 274.78,-23.05 274.33,-23.05 273.46,-22.88 271.23,-23.65 270.48,-24.25 268.53,-26.15 265.23,-37.67 263.99,-38.69 263.69,-38.74 262.77,-38.73 260.85,-39.4 258.57,-39.37 257.46,-39.76 257.1,-39.82 256.06,-40.85 255.82,-42.25 256.12,-43.96 255.6,-46.9 256.08,-49.63 255.79,-51.3 255.88,-51.84 255.88,-52.81 254.94,-53.75 254.27,-53.75 253.86,-53.34 253.33,-50.29 252.48,-49.43 251.43,-49.16 249.33,-49.71 249.01,-49.71 248.89,-49.58
  TOP w0.152: 248.89,-49.58 P_CPU_OCP_9_P.1
PE_CPU_OCP_10_DN: length 58.9
  TOP w0.127: P_OCP2.B50 274.93,-21.71 274.78,-21.56 274.32,-21.56 273.19,-21.76 273.17,-21.76 271,-22.35 268.93,-24.23 267.17,-25.98 264.27,-35.5 262.92,-36.58 262.21,-36.72 261.15,-37.15 258.86,-37.22 256.74,-38.07 254.46,-38.14 252.33,-38.99 250.05,-39.06 247.93,-39.91 245.95,-39.97 245.18,-40.28 245.17,-40.28 244.8,-41.05 244.47,-42.18 243.13,-44.03 242.5,-46.23 241.42,-47.71 241.33,-48.05 240.6,-48.77 237.82,-49.25 237.58,-49.25 237.46,-49.38
  TOP w0.152: 237.46,-49.38 P_CPU_OCP_10_N.1
PE_CPU_OCP_10_DP: length 58.9
  TOP w0.127: P_OCP2.B51 274.93,-21.11 274.78,-21.25 274.29,-21.25 273.13,-21.46 273.1,-21.46 270.85,-22.08 268.72,-24.01 266.9,-25.82 264.01,-35.32 262.79,-36.29 262.12,-36.43 261.09,-36.84 258.8,-36.92 256.68,-37.77 254.39,-37.84 252.27,-38.69 249.99,-38.76 247.86,-39.61 245.89,-39.67 245.09,-39.99 244.96,-40.02 244.51,-40.95 244.2,-42.04 242.85,-43.89 242.22,-46.09 241.14,-47.58 241.05,-47.88 240.46,-48.48 237.79,-48.95 237.58,-48.95 237.46,-48.82
  TOP w0.152: 237.46,-48.82 P_CPU_OCP_10_P.1
PE_CPU_OCP_11_DN: length 58.9
  TOP w0.127: 260.32,-27.28 260.44,-27.15 261.04,-27.15 261.51,-26.69 261.51,-25.76 261.65,-25.62 262.18,-25.62 262.32,-25.76 262.32,-26.05 262.94,-26.67 262.94,-27.36 261.98,-28.32 261.98,-28.6 262.08,-29.19 261.98,-29.78 261.98,-30.04 262.45,-30.51 262.71,-30.51 263.14,-30.44 263.58,-30.51 263.83,-30.51 264.64,-29.7 264.64,-28.46 264.85,-27.31 264.64,-26.16 264.64,-25.68 263.96,-25 263.96,-24.74 263.85,-24.1 264.16,-22.34 263.76,-20.09 263.96,-18.96 263.96,-18.55 264.16,-18.34 265.2,-18.34 265.35,-18.49 265.35,-18.89 265.15,-20.04 265.55,-22.29 265.35,-23.39 265.35,-23.81 265.97,-24.43 266.83,-24.43 267.46,-23.79 267.46,-23.51 267.66,-22.39 267.26,-20.15 267.46,-19.03 267.46,-18.65 267.66,-18.44 268.55,-18.44 268.76,-18.65 268.76,-19 268.57,-20.08 268.76,-21.16 268.76,-21.52 269.09,-21.85 269.57,-21.85 270.7,-20.72 270.7,-20.04 270.44,-19.77 270.44,-18.67 270.57,-18.54 270.81,-18.54 271.45,-19.18 271.45,-19.61 271.89,-20.06 272.33,-20.06 272.62,-19.76 274.78,-19.76 274.93,-19.91 P_OCP2.B53
  TOP w0.152: 260.32,-27.28 P_CPU_OCP_11_N.1
PE_CPU_OCP_11_DP: length 58.9
  TOP w0.127: 260.32,-26.72 260.44,-26.85 260.91,-26.85 261.2,-26.56 261.2,-25.63 261.52,-25.31 262.31,-25.31 262.62,-25.63 262.62,-25.92 263.25,-26.54 263.25,-27.49 262.28,-28.45 262.28,-28.58 262.39,-29.19 262.28,-29.81 262.28,-29.91 262.58,-30.21 262.68,-30.21 263.14,-30.13 263.6,-30.21 263.7,-30.21 264.34,-29.57 264.34,-28.44 264.54,-27.31 264.34,-26.19 264.34,-25.81 263.65,-25.12 263.65,-24.77 263.54,-24.1 263.85,-22.34 263.45,-20.09 263.65,-18.94 263.65,-18.42 264.03,-18.04 265.33,-18.04 265.66,-18.37 265.66,-18.91 265.46,-20.04 265.86,-22.29 265.66,-23.41 265.66,-23.68 266.1,-24.12 266.7,-24.12 267.16,-23.67 267.16,-23.48 267.35,-22.39 266.95,-20.15 267.16,-19 267.16,-18.52 267.54,-18.14 268.68,-18.14 269.06,-18.52 269.06,-19.03 268.88,-20.08 269.06,-21.14 269.06,-21.39 269.21,-21.54 269.45,-21.54 270.4,-20.59 270.4,-20.17 270.13,-19.9 270.13,-18.54 270.44,-18.24 270.94,-18.24 271.75,-19.05 271.75,-19.49 272.02,-19.75 272.2,-19.75 272.5,-19.45 274.78,-19.45 274.93,-19.31 P_OCP2.B54
  TOP w0.152: 260.32,-26.72 P_CPU_OCP_11_P.1
PE_CPU_OCP_12_DN: length 58.9
  TOP w0.127: P_OCP2.B56 274.93,-18.11 274.78,-17.96 272.24,-17.96 271.09,-16.82 269.75,-16.82 268.62,-16.62 266.37,-17.02 264.12,-16.62 261.87,-17.02 260.74,-16.82 260.21,-16.82 259.09,-16.62 257.48,-16.9 256.99,-16.82 256.73,-16.82 256.16,-17.39 256.12,-17.44 255.73,-19.65 256.19,-22.28 255.81,-24.44 256.25,-26.94 255.81,-29.42 256.37,-32.61 256.02,-34.61 255.27,-35.36 254.28,-35.36 253.25,-34.33 253.06,-33.22 253.41,-31.23 252.68,-27.08 252.12,-26.52 251.87,-26.52 251.41,-26.44 250.96,-26.52 250.67,-26.52 250.04,-27.15 249.01,-27.15 248.89,-27.28
  TOP w0.152: 248.89,-27.28 P_CPU_OCP_12_N.1
PE_CPU_OCP_12_DP: length 58.9
  TOP w0.127: 248.89,-26.72 249.01,-26.85 249.91,-26.85 250.55,-26.22 250.93,-26.22 251.41,-26.13 251.89,-26.22 252.25,-26.22 252.96,-26.93 253.72,-31.23 253.37,-33.22 253.54,-34.19 254.41,-35.06 255.14,-35.06 255.74,-34.46 256.06,-32.61 255.5,-29.42 255.94,-26.94 255.5,-24.44 255.88,-22.28 255.42,-19.65 255.83,-17.29 255.99,-17.13 256.61,-16.51 257.02,-16.51 257.48,-16.59 259.09,-16.31 260.24,-16.51 260.77,-16.51 261.87,-16.71 264.12,-16.31 266.37,-16.71 268.62,-16.31 269.78,-16.51 271.22,-16.51 272.36,-17.65 274.78,-17.65 274.93,-17.51 P_OCP2.B57
  TOP w0.152: 248.89,-26.72 P_CPU_OCP_12_P.1
